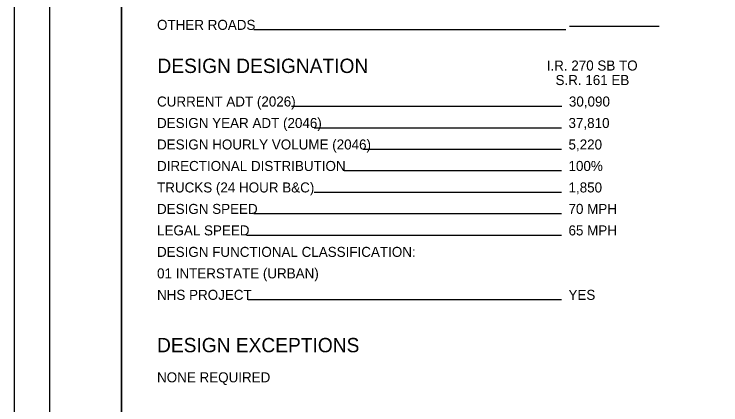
# Model space of a CAD drawing. Extents: x 0 to 34, y 0 to 22.
# Drawn here: x 0 to 9.86, y 5.64 to 11.1 of the extents above; entities that cross this region are included whole.
import ezdxf

# ---------------------------------------------------------------- set-up
doc = ezdxf.new("R2010")
doc.units = 0
for name, color, linetype in [('SH_Border', 7, 'Continuous'), ('SH_Cut_Line', 7, 'Continuous'), ('SH_Data', 7, 'Continuous'), ('SH_Text', 7, 'Continuous')]:
    doc.layers.add(name, color=color, linetype=linetype)

msp = doc.modelspace()

# ---------------------------------------------------------------- linework, layer by layer
at = {"layer": 'SH_Border'}
for points in [[(0.5, 21.5), (1.5, 21.5), (1.5, 0.5), (0.5, 0.5)], [(1.5, 21.5), (33.5, 21.5), (33.5, 0.5), (1.5, 0.5)]]:
    msp.add_lwpolyline(points, close=True, dxfattribs=at)
at = {"layer": 'SH_Cut_Line'}
msp.add_lwpolyline([(0, 0), (34, 0), (34, 22), (0, 22)], close=True, dxfattribs=at)
at = {"layer": 'SH_Data'}
for p, q in [((7.7, 10.8767), (3.3471, 10.8767)), ((9, 10.9223), (7.75, 10.9223)), ((7.6424, 9.8062), (3.871, 9.8062)), ((7.6368, 9.5062), (4.1885, 9.5062)), ((7.6368, 9.2062), (4.8723, 9.2062)), ((7.6368, 8.9062), (4.6037, 8.9062)), ((7.6368, 8.6062), (4.1885, 8.6062)), ((7.6368, 8.3062), (3.346, 8.3062)), ((7.6368, 8.0062), (3.2422, 8.0062)), ((7.6368, 7.1062), (3.2669, 7.1062))]:
    msp.add_line(p, q, dxfattribs=at)

# ---------------------------------------------------------------- texts
msp.add_text('DESIGN DESIGNATION', height=0.2, dxfattribs=at).set_placement((2, 10.2747))
at = {"layer": 'SH_Text'}
for s, height, p in [('OTHER ROADS', 0.14, (1.9944, 10.8767)), ('I.R. 270 SB TO', 0.14, (7.4326, 10.3087)), ('S.R. 161 EB', 0.14, (7.5557, 10.1062)), ('CURRENT ADT (2026)', 0.14, (1.9944, 9.8062)), ('30,090', 0.14, (7.7424, 9.8062)), ('DESIGN YEAR ADT (2046)', 0.14, (1.9944, 9.5062)), ('37,810', 0.14, (7.7368, 9.5062)), ('DESIGN HOURLY VOLUME (2046)', 0.14, (1.9944, 9.2062)), ('5,220', 0.14, (7.7368, 9.2062)), ('DIRECTIONAL DISTRIBUTION', 0.14, (1.9944, 8.9062)), ('100%', 0.14, (7.7368, 8.9062)), ('TRUCKS (24 HOUR B&C)', 0.14, (1.9944, 8.6062)), ('1,850', 0.14, (7.7368, 8.6062)), ('DESIGN SPEED', 0.14, (1.9944, 8.3062)), ('70 MPH', 0.14, (7.7368, 8.3062)), ('LEGAL SPEED', 0.14, (1.9944, 8.0062)), ('65 MPH', 0.14, (7.7368, 8.0062)), ('DESIGN FUNCTIONAL CLASSIFICATION:', 0.14, (1.9944, 7.7062)), ('01 INTERSTATE (URBAN)', 0.14, (1.9944, 7.4062)), ('NHS PROJECT', 0.14, (1.9944, 7.1062)), ('YES', 0.14, (7.7368, 7.1062)), ('DESIGN EXCEPTIONS', 0.2, (1.9944, 6.3744)), ('NONE REQUIRED', 0.14, (1.9944, 5.9544))]:
    msp.add_text(s, height=height, dxfattribs=at).set_placement(p)

doc.saveas('drawing.dxf')
